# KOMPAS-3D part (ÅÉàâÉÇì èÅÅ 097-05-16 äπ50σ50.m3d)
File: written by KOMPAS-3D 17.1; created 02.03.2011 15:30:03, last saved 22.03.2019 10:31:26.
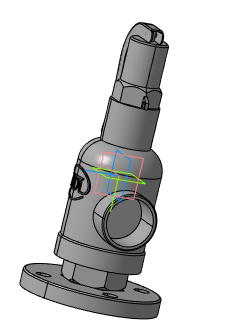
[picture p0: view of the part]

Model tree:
1. Плоскость XY
2. Плоскость ZX
3. Плоскость ZY
4. Ось X
5. Ось Y
6. Ось Z
7. Начало координат
8. Операция без истории:2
